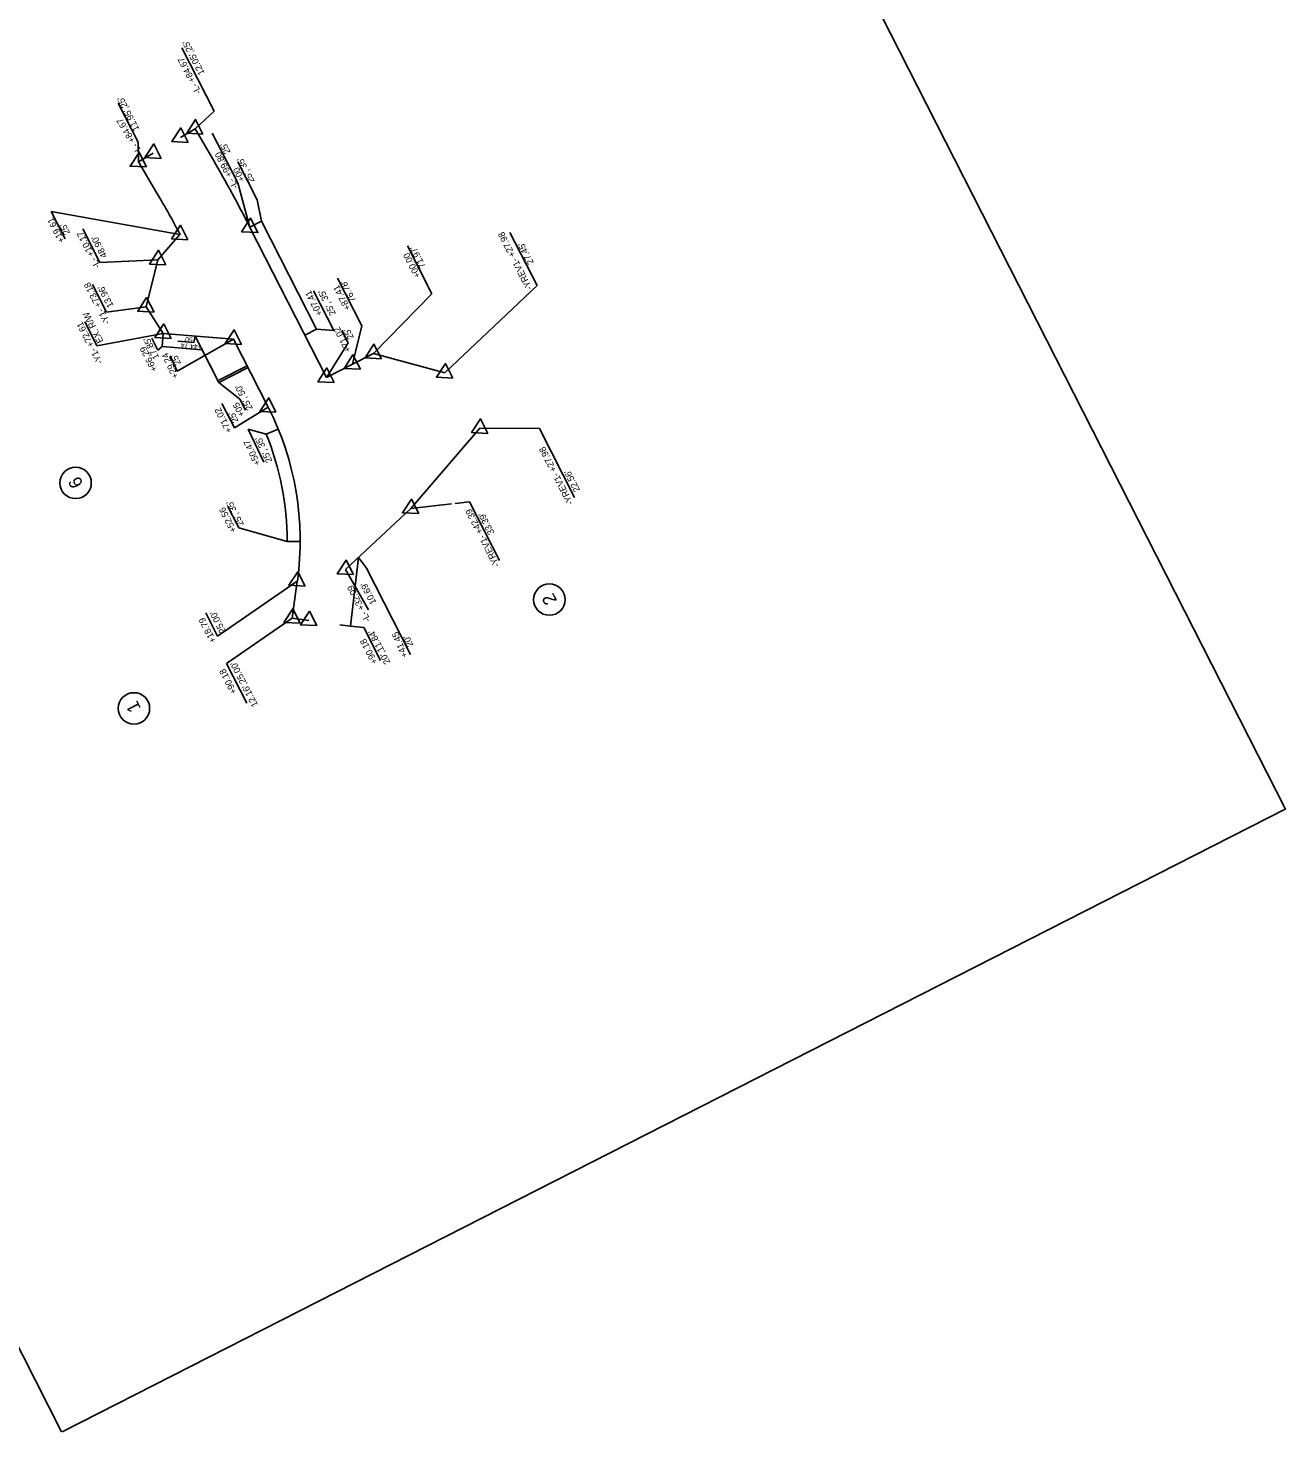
# Model space of a CAD drawing. Extents: x 558638 to 560135, y 514715 to 516498.
# Drawn here: x 559174 to 560135, y 514715 to 515789 of the extents above; entities that cross this region are included whole.
import ezdxf

# ---------------------------------------------------------------- set-up
doc = ezdxf.new("R2010")
doc.units = 0
for name, color, linetype in [('Prop Easement Construction', 7, 'Continuous'), ('Prop Easement Construction Station Offsets', 7, 'Continuous'), ('Prop Easement Permanent Drainage', 7, 'Continuous'), ('Prop Easement Permanent Drainage Station Offsets', 7, 'Continuous'), ('Prop Parcel Number CELL', 7, 'Continuous'), ('Prop Parcel Number Text', 7, 'Continuous'), ('Prop ROW Marker CELL', 7, 'Continuous'), ('Prop ROW RW Lines', 7, 'Continuous'), ('Prop ROW Station Offsets', 7, 'Continuous'), ('Scratch_Level_3', 7, 'Continuous'), ('Scratch_Level_4', 7, 'Continuous'), ('Sheet Layout Plan Border', 7, 'Continuous')]:
    doc.layers.add(name, color=color, linetype=linetype)

msp = doc.modelspace()

# ---------------------------------------------------------------- linework, layer by layer
at = {"layer": 'Prop Easement Construction'}
for p, q in [((559343.3, 515636.6), (559352.2, 515641.1)), ((559394.2, 515558.6), (559352.2, 515641.1)), ((559385.3, 515554.1), (559394.2, 515558.6)), ((559277.1, 515555.4), (559276.3, 515545.4)), ((559306.9, 515542.8), (559276.3, 515545.4)), ((559365, 515482.2), (559355.7, 515478.4)), ((559381.8, 515396.2), (559371.8, 515396.3)), ((559420.3, 515331.4), (559426.5, 515384.1)), ((559412.2, 515332.5), (559420.3, 515331.4))]:
    msp.add_line(p, q, dxfattribs=at)
msp.add_arc((559156.8, 515396.9), 215, 359.8333, 22.2727, dxfattribs=at)
at = {"layer": 'Prop Easement Construction Station Offsets'}
for p, q in [((559348.8, 515657.4), (559334, 515686.5)), ((559352.2, 515641.1), (559348.8, 515657.4)), ((559407.4, 515557.7), (559392, 515588)), ((559394.2, 515558.6), (559407.4, 515557.7)), ((559273, 515542.5), (559268.4, 515551.6)), ((559276.3, 515545.4), (559273, 515542.5)), ((559355.7, 515478.4), (559342, 515482)), ((559342, 515482), (559353.9, 515456.9)), ((559334.9, 515406.7), (559326.5, 515423.1)), ((559371.8, 515396.3), (559334.9, 515406.7)), ((559426.5, 515384.1), (559432.6, 515375.9)), ((559432.6, 515375.9), (559466.2, 515309.8)), ((559420.3, 515331.4), (559430.4, 515330.5)), ((559430.4, 515330.5), (559443.3, 515305.1))]:
    msp.add_line(p, q, dxfattribs=at)
at = {"layer": 'Prop Easement Permanent Drainage'}
for p, q in [((559300.4, 515548.4), (559288.3, 515549.4)), ((559319.6, 515517.9), (559301.6, 515553.3)), ((559341.9, 515529.3), (559319.6, 515517.9))]:
    msp.add_line(p, q, dxfattribs=at)
at = {"layer": 'Prop Easement Permanent Drainage Station Offsets'}
for p, q in [((559301.6, 515553.3), (559300.4, 515548.4)), ((559319.6, 515517.9), (559335.6, 515505)), ((559339.9, 515496.6), (559335.6, 515505))]:
    msp.add_line(p, q, dxfattribs=at)
at = {"layer": 'Prop Parcel Number CELL'}
for p, q in [((559210.1, 515441), (559210.1, 515441)), ((559572.3, 515351.8), (559572.3, 515351.8)), ((559254.7, 515268.6), (559254.7, 515268.6))]:
    msp.add_line(p, q, dxfattribs=at)
for centre in [(559210.1, 515441), (559572.3, 515351.8), (559254.7, 515268.6)]:
    msp.add_circle(centre, 12, dxfattribs=at)
at = {"layer": 'Prop ROW Marker CELL'}
for p, q in [((559301.4, 515711.8), (559301.4, 515711.8)), ((559290.2, 515705.3), (559290.2, 515705.3)), ((559258.2, 515686.6), (559258.2, 515686.6)), ((559269.5, 515693.1), (559269.5, 515693.1)), ((559343.4, 515636.4), (559343.4, 515636.4)), ((559289.9, 515630.9), (559289.9, 515630.9)), ((559273, 515611.7), (559273, 515611.7)), ((559264, 515575.6), (559264, 515575.6)), ((559277.1, 515555.4), (559277.1, 515555.4)), ((559330.9, 515550.9), (559330.9, 515550.9)), ((559437.8, 515540), (559437.8, 515540)), ((559421.7, 515531.8), (559421.7, 515531.8)), ((559492.4, 515525.1), (559492.4, 515525.1)), ((559401.8, 515521.7), (559401.8, 515521.7)), ((559357.3, 515499), (559357.3, 515499)), ((559519.2, 515482.9), (559519.2, 515482.9)), ((559466.4, 515421.5), (559466.4, 515421.5)), ((559416.5, 515374.8), (559416.5, 515374.8)), ((559379.6, 515365.9), (559379.6, 515365.9)), ((559375.7, 515337.6), (559375.7, 515337.6)), ((559388.4, 515335.8), (559388.4, 515335.8))]:
    msp.add_line(p, q, dxfattribs=at)
for points in [[(559307.4, 515707.8), (559295, 515708.5), (559301.8, 515719)], [(559296.2, 515701.4), (559283.7, 515702.1), (559290.5, 515712.5)], [(559275.6, 515689.2), (559263.1, 515689.8), (559269.9, 515700.3)], [(559264.2, 515682.7), (559251.8, 515683.3), (559258.6, 515693.8)], [(559337, 515633.1), (559343.8, 515643.6), (559349.5, 515632.5)], [(559296, 515626.9), (559283.5, 515627.6), (559290.3, 515638.1)], [(559279.1, 515607.7), (559266.6, 515608.4), (559273.4, 515618.9)], [(559270.1, 515571.6), (559257.6, 515572.3), (559264.4, 515582.8)], [(559283.2, 515551.4), (559270.7, 515552.1), (559277.5, 515562.6)], [(559336.9, 515546.9), (559324.5, 515547.6), (559331.2, 515558.1)], [(559443.9, 515536), (559431.4, 515536.7), (559438.2, 515547.2)], [(559427.8, 515527.9), (559415.3, 515528.5), (559422.1, 515539)], [(559407.9, 515517.7), (559395.4, 515518.4), (559402.2, 515528.9)], [(559498.5, 515521.2), (559486, 515521.9), (559492.8, 515532.3)], [(559363.3, 515495), (559350.9, 515495.7), (559357.7, 515506.2)], [(559525.2, 515478.9), (559512.8, 515479.6), (559519.6, 515490.1)], [(559472.5, 515417.5), (559460, 515418.2), (559466.8, 515428.7)], [(559422.6, 515370.9), (559410.1, 515371.5), (559416.9, 515382)], [(559385.7, 515362), (559373.2, 515362.7), (559380, 515373.1)], [(559381.7, 515333.7), (559369.3, 515334.3), (559376.1, 515344.8)], [(559388.9, 515343), (559394.4, 515331.9), (559382, 515332.6)]]:
    msp.add_lwpolyline(points, close=True, dxfattribs=at)
at = {"layer": 'Prop ROW RW Lines'}
for p, q in [((559290.2, 515705.3), (559301.4, 515711.8)), ((559315.4, 515687.8), (559301.4, 515711.8)), ((559269.5, 515693.1), (559258.2, 515686.6)), ((559272.2, 515662.6), (559258.2, 515686.6)), ((559401.8, 515521.7), (559343.4, 515636.4)), ((559273, 515611.7), (559289.9, 515630.9)), ((559264, 515575.6), (559273, 515611.7)), ((559277.1, 515555.4), (559264, 515575.6)), ((559330.9, 515550.9), (559277.1, 515555.4)), ((559357.3, 515499), (559330.9, 515550.9)), ((559421.7, 515531.8), (559437.8, 515540)), ((559437.8, 515540), (559492.4, 515525.1)), ((559401.8, 515521.7), (559421.7, 515531.8)), ((559466.4, 515421.5), (559519.2, 515482.9)), ((559416.5, 515374.8), (559466.4, 515421.5)), ((559375.7, 515337.6), (559379.6, 515365.9)), ((559375.7, 515337.6), (559388.4, 515335.8))]:
    msp.add_line(p, q, dxfattribs=at)
for centre, radius, start, end in [((558430, 515171.4), 1025, 26.9821, 30.2524), ((558827.5, 515393.4), 519.9, 27.1823, 31.1873), ((559156.8, 515396.9), 225, 352.0938, 26.9819)]:
    msp.add_arc(centre, radius, start, end, dxfattribs=at)
at = {"layer": 'Prop ROW Station Offsets'}
for p, q in [((559315.9, 515725.4), (559291.3, 515773.7)), ((559257.9, 515701.7), (559242.7, 515731.5)), ((559301.4, 515711.8), (559315.9, 515725.4)), ((559334, 515670.5), (559314.6, 515708.6)), ((559258.2, 515686.6), (559257.9, 515701.7)), ((559343.4, 515636.4), (559334, 515670.5)), ((559289.9, 515630.9), (559191.5, 515648.6)), ((559202.1, 515627.8), (559191.5, 515648.6)), ((559228.6, 515609.5), (559215.5, 515635.3)), ((559562.9, 515591.9), (559542.2, 515632.6)), ((559482.5, 515585.7), (559463.8, 515622.4)), ((559273, 515611.7), (559228.6, 515609.5)), ((559233.8, 515571.5), (559223, 515592.7)), ((559428.9, 515561.1), (559410.4, 515597.5)), ((559492.4, 515525.1), (559562.9, 515591.9)), ((559437.8, 515540), (559482.5, 515585.7)), ((559264, 515575.6), (559233.8, 515571.5)), ((559226.3, 515546.2), (559217.1, 515564.3)), ((559418.6, 515548.1), (559413.7, 515557.7)), ((559421.7, 515531.8), (559428.9, 515561.1)), ((559277.1, 515555.4), (559226.4, 515545.9)), ((559330.9, 515550.9), (559287.8, 515526.5)), ((559401.8, 515521.7), (559418.6, 515548.1)), ((559287.8, 515526.5), (559282.4, 515538.2)), ((559331.5, 515483.1), (559322, 515501.8)), ((559357.3, 515499), (559331.5, 515483.1)), ((559519.2, 515482.9), (559564.7, 515482.6)), ((559564.7, 515482.6), (559591.5, 515429.9)), ((559466.4, 515421.5), (559497.6, 515425)), ((559500.2, 515425.3), (559511.3, 515426.6)), ((559511.3, 515426.6), (559534.1, 515381.7)), ((559434.1, 515344), (559416.5, 515374.8)), ((559379.6, 515365.9), (559318.6, 515323.9)), ((559318.6, 515323.9), (559309.6, 515341.6)), ((559375.7, 515337.6), (559325.5, 515303)), ((559341, 515272.6), (559325.5, 515303))]:
    msp.add_line(p, q, dxfattribs=at)
at = {"layer": 'Scratch_Level_3'}
for p, q in [((559437.8, 515540), (559492.4, 515525.1)), ((559401.8, 515521.7), (559421.7, 515531.8))]:
    msp.add_line(p, q, dxfattribs=at)
at = {"layer": 'Scratch_Level_4'}
for p, q in [((559318.9, 515519.3), (559306.1, 515544.4)), ((559341.2, 515530.6), (559319.7, 515519.7))]:
    msp.add_line(p, q, dxfattribs=at)
at = {"layer": 'Sheet Layout Plan Border'}
for p, q in [((560135.1, 515191.6), (559470.2, 516497.6)), ((558638, 515817.8), (559199.4, 514715.3)), ((559199.7, 514715.4), (560135.5, 515191.8))]:
    msp.add_line(p, q, dxfattribs=at)

# ---------------------------------------------------------------- texts
at = {"layer": 'Prop Easement Construction Station Offsets'}
for s, rotation, p in [("25', 35'", 116.9819, (559347.1, 515671.7)), ('+00', 116.9819, (559339.8, 515672.9)), ('+07.41', 116.9819, (559399.1, 515570.3)), ("25', 35'", 116.9819, (559409.3, 515570.5)), ("17.85'", 116.9819, (559274.2, 515537)), ('+66.29', 116.9819, (559272.7, 515527.6)), ('+50.47', 115.2922, (559351.6, 515455.8)), ("25', 35'", 115.2922, (559360.6, 515457.9)), ('+52.56', 116.9819, (559333.3, 515404.6)), ("25', 35'", 116.9819, (559338.9, 515409.3)), ('+90.18', 116.9819, (559441.1, 515304)), ("20',11.84'", 116.9819, (559450.9, 515303.8)), ('+41.45', 112.581, (559464.2, 515308.6)), ("20'", 112.581, (559468.3, 515316.8))]:
    msp.add_text(s, height=5, rotation=rotation, dxfattribs=at).set_placement(p)
at = {"layer": 'Prop Easement Permanent Drainage Station Offsets'}
for s, height, rotation, p in [('+44.74', 3.75, 176.6166, (559306.6, 515547)), ("50'", 3.75, 176.6166, (559299.7, 515552.3)), ("25', 50'", 5, 116.9819, (559345.7, 515498)), ('+05', 5, 116.9819, (559339.6, 515493.1))]:
    msp.add_text(s, height=height, rotation=rotation, dxfattribs=at).set_placement(p)
at = {"layer": 'Prop Parcel Number Text'}
for s, p in [('6', (559216.2, 515440.1)), ('2', (559578.4, 515350.9)), ('1', (559260.3, 515268.6))]:
    msp.add_text(s, height=10, rotation=116.9819, dxfattribs=at).set_placement(p)
at = {"layer": 'Prop ROW Station Offsets'}
for s, rotation, p in [("12.05',25'", 116.9819, (559308.9, 515754.5)), ('-L- +84.67', 116.9819, (559306.3, 515739.8)), ("11.95',25'", 116.9819, (559259, 515711.6)), ('-L- +84.67', 120.9557, (559261.1, 515694.3)), (" 25'", 116.9819, (559329.5, 515692.4)), ('-L- +99.80', 116.9819, (559334.6, 515667.4)), ('+19.61', 116.9819, (559201.9, 515626.1)), ("25'", 116.9819, (559206, 515632.3)), ('-L- +10.17', 116.9819, (559229.1, 515606.6)), ('-YREV1- +27.98', 116.9819, (559559.4, 515590)), ("48.90'", 116.9819, (559234.4, 515614.6)), ("71.97'", 116.9819, (559478, 515606.7)), ("27.45'", 116.9819, (559560.5, 515609.5)), ('+00.00', 116.9819, (559474.1, 515599.2)), ('-Y1- +73.18', 116.9819, (559236.6, 515563.7)), ("13.96'", 116.9819, (559239.3, 515576.6)), ('+87.41', 116.9819, (559420.5, 515574.5)), ("76.78'", 116.9819, (559424.6, 515580.6)), ('EX. R/W', 116.9819, (559231.5, 515549.5)), ('-Y1- +72.61', 116.9819, (559231, 515533.4)), ('+71.02', 116.9819, (559421, 515542.5)), ("25'", 116.9819, (559423, 515552.2)), ('+29.24', 115.0362, (559289, 515522.3)), ("25'", 115.0362, (559290.8, 515532.3)), ('+71.02', 116.9819, (559329.9, 515480.7)), ("25'", 116.9819, (559334.8, 515488.4)), ('-YREV1- +27.98', 116.9819, (559590.8, 515425.7)), ("22.56'", 116.9819, (559595.9, 515435.5)), ('-YREV1- +42.39', 116.9819, (559534.5, 515378.2)), ("33.39'", 116.9819, (559530.4, 515402.9)), ("10.69'", 116.9819, (559440.2, 515349.5)), ('-L- +32.09', 116.9819, (559435.8, 515336.1)), ("25.00'", 116.9819, (559325.1, 515327.6)), ('+18.79', 116.9819, (559317.7, 515320.2)), ('+90.18', 116.9819, (559333.5, 515281)), ("12.16',25.00'", 116.9819, (559349.7, 515271.2))]:
    msp.add_text(s, height=5, rotation=rotation, dxfattribs=at).set_placement(p)

doc.saveas('drawing.dxf')
